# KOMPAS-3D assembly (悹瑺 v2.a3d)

Referenced files in D:\Dropbox\Copter\Frame\: Центр плата v.2.m3d, Полка контроллера v.2.m3d, Луч.m3d, Полка GPS v.2.m3d
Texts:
  Рама v2
  (ф) Центр плата v.2 верх (1)
  (+) Полка контроллера
  (+) Луч (1)
  (+) Луч (2)
  (+) Луч (3)
  (+) Луч (4)
  (+) Центр плата v.2 верх (2)
  (+) Полка GPS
